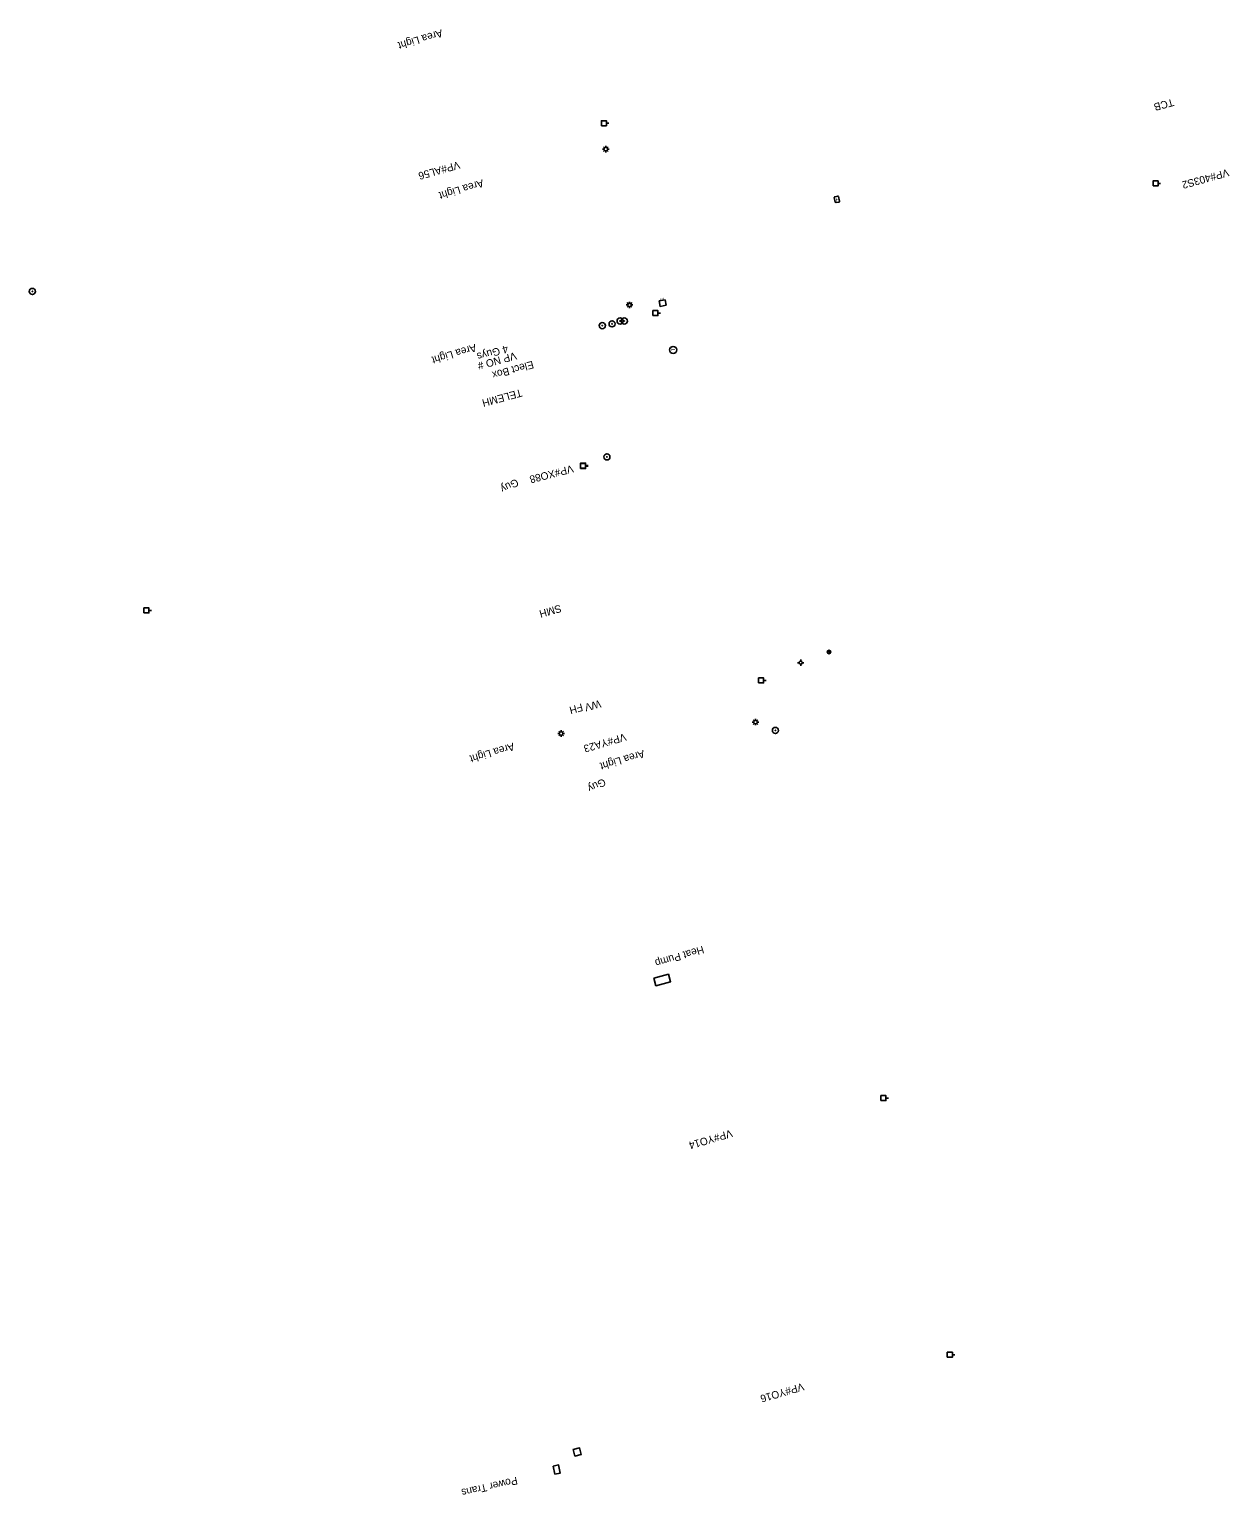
# Model space of a CAD drawing. Extents: x 3872070 to 3879223, y 293944 to 310567.
# Drawn here: x 3875879 to 3876357, y 294304 to 294887 of the extents above; entities that cross this region are included whole.
import ezdxf

# ---------------------------------------------------------------- set-up
doc = ezdxf.new("R2010")
doc.units = 0
for name, color, linetype in [('Level 33', 7, 'Continuous'), ('Level 34', 7, 'Continuous'), ('Level 35', 7, 'Continuous'), ('Level 37', 7, 'Continuous'), ('Level 39', 7, 'Continuous'), ('Level 4', 7, 'Continuous'), ('Level 5', 7, 'Continuous'), ('Level 7', 7, 'Continuous'), ('Level 9', 7, 'Continuous')]:
    doc.layers.add(name, color=color, linetype=linetype)

msp = doc.modelspace()

# ---------------------------------------------------------------- linework, layer by layer
at = {"layer": 'Level 4'}
for p, q in [((3876108.78, 294849.79), (3876109.78, 294849.79)), ((3876107.78, 294839.51), (3876107.2, 294839.51)), ((3876107.99, 294840.03), (3876107.58, 294840.43)), ((3876107.58, 294838.59), (3876107.99, 294839)), ((3876108.5, 294840.24), (3876108.5, 294840.81)), ((3876108.5, 294838.79), (3876108.5, 294838.21)), ((3876109.01, 294840.03), (3876109.42, 294840.43)), ((3876109.42, 294838.59), (3876109.01, 294839)), ((3876109.23, 294839.51), (3876109.8, 294839.51)), ((3876328.28, 294825.87), (3876329.28, 294825.87)), ((3876117.25, 294777.5), (3876116.68, 294777.5)), ((3876117.46, 294778.01), (3876117.06, 294778.42)), ((3876117.06, 294776.58), (3876117.46, 294776.99)), ((3876117.98, 294778.23), (3876117.98, 294778.8)), ((3876117.98, 294776.78), (3876117.98, 294776.2)), ((3876118.49, 294778.01), (3876118.9, 294778.42)), ((3876118.9, 294776.58), (3876118.49, 294776.99)), ((3876118.7, 294777.5), (3876119.28, 294777.5)), ((3876129.24, 294774.26), (3876130.24, 294774.26)), ((3876100.49, 294713.59), (3876101.49, 294713.59)), ((3876100.51, 294713.37), (3876101.51, 294713.37)), ((3875926.71, 294655.95), (3875927.71, 294655.95)), ((3876171.33, 294628.13), (3876172.33, 294628.13)), ((3876167.36, 294611.53), (3876166.79, 294611.53)), ((3876167.58, 294612.04), (3876167.17, 294612.44)), ((3876167.17, 294610.61), (3876167.58, 294611.01)), ((3876168.09, 294612.25), (3876168.09, 294612.83)), ((3876168.6, 294612.04), (3876169.01, 294612.44)), ((3876169.01, 294610.61), (3876168.6, 294611.01)), ((3876168.81, 294611.53), (3876169.39, 294611.53)), ((3876090, 294606.98), (3876089.43, 294606.98)), ((3876090.21, 294607.5), (3876089.81, 294607.9)), ((3876089.81, 294606.06), (3876090.21, 294606.47)), ((3876090.73, 294607.71), (3876090.73, 294608.28)), ((3876090.73, 294606.26), (3876090.73, 294605.68)), ((3876091.24, 294607.5), (3876091.65, 294607.9)), ((3876091.65, 294606.06), (3876091.24, 294606.47)), ((3876091.45, 294606.98), (3876092.03, 294606.98)), ((3876168.09, 294610.8), (3876168.09, 294610.23)), ((3876220.01, 294461.91), (3876221.01, 294461.91)), ((3876246.42, 294359.79), (3876247.42, 294359.79))]:
    msp.add_line(p, q, dxfattribs=at)
for points in [[(3876106.78, 294848.79), (3876106.78, 294850.79), (3876108.78, 294850.79), (3876108.78, 294848.79)], [(3876326.28, 294824.87), (3876326.28, 294826.87), (3876328.28, 294826.87), (3876328.28, 294824.87)], [(3876127.24, 294773.26), (3876127.24, 294775.26), (3876129.24, 294775.26), (3876129.24, 294773.26)], [(3876132.51, 294777.36), (3876130.15, 294776.95), (3876129.77, 294779.1), (3876132.14, 294779.51)], [(3876098.49, 294712.59), (3876098.49, 294714.59), (3876100.49, 294714.59), (3876100.49, 294712.59)], [(3876098.51, 294712.37), (3876098.51, 294714.37), (3876100.51, 294714.37), (3876100.51, 294712.37)], [(3875924.71, 294654.95), (3875924.71, 294656.95), (3875926.71, 294656.95), (3875926.71, 294654.95)], [(3876169.33, 294627.13), (3876169.33, 294629.13), (3876171.33, 294629.13), (3876171.33, 294627.13)], [(3876218.01, 294460.91), (3876218.01, 294462.91), (3876220.01, 294462.91), (3876220.01, 294460.91)], [(3876244.42, 294358.79), (3876244.42, 294360.79), (3876246.42, 294360.79), (3876246.42, 294358.79)]]:
    msp.add_lwpolyline(points, close=True, dxfattribs=at)
for points in [[(3876127.65, 294509.56), (3876133.46, 294511.18), (3876134.29, 294508.21), (3876128.48, 294506.59), (3876127.65, 294509.56)], [(3876095.55, 294322.01), (3876098.08, 294322.69), (3876098.78, 294320.1), (3876096.25, 294319.42), (3876095.55, 294322.01)], [(3876087.59, 294315.47), (3876089.74, 294315.93), (3876090.43, 294312.72), (3876088.28, 294312.26), (3876087.59, 294315.47)]]:
    msp.add_lwpolyline(points, dxfattribs=at)
for centre, radius in [((3876108.5, 294839.51), 0.725), ((3875880.35, 294782.87), 1.22), ((3875880.35, 294782.87), 0.0992), ((3875880.35, 294782.87), 0.0483), ((3876117.98, 294777.5), 0.725), ((3876107.13, 294769.28), 1.22), ((3876107.13, 294769.28), 0.0992), ((3876107.13, 294769.28), 0.0483), ((3876111.03, 294769.99), 1.22), ((3876111.03, 294769.99), 0.0992), ((3876111.03, 294769.99), 0.0483), ((3876114.23, 294771.12), 1.22), ((3876114.23, 294771.12), 0.0992), ((3876114.23, 294771.12), 0.0483), ((3876115.89, 294771.1), 1.22), ((3876115.89, 294771.1), 0.0992), ((3876115.89, 294771.1), 0.0483), ((3876108.96, 294717.06), 1.22), ((3876108.96, 294717.06), 0.0992), ((3876108.96, 294717.06), 0.0483), ((3876168.09, 294611.53), 0.725), ((3876090.73, 294606.98), 0.725), ((3876176.03, 294608.18), 1.22), ((3876176.03, 294608.18), 0.0992), ((3876176.03, 294608.18), 0.0483)]:
    msp.add_circle(centre, radius, dxfattribs=at)
at = {"layer": 'Level 5'}
for p, q in [((3876184.82, 294635.15), (3876185.44, 294635.15)), ((3876186.07, 294636.4), (3876186.07, 294635.76)), ((3876186.07, 294634.52), (3876186.07, 294633.9)), ((3876186.68, 294635.15), (3876187.32, 294635.15)), ((3876196.47, 294639.41), (3876196.83, 294639.41)), ((3876196.83, 294639.41), (3876197.83, 294639.41)), ((3876197.83, 294639.41), (3876198.2, 294639.41))]:
    msp.add_line(p, q, dxfattribs=at)
for centre, radius in [((3876197.33, 294639.41), 0.7), ((3876186.07, 294635.15), 0.625)]:
    msp.add_circle(centre, radius, dxfattribs=at)
msp.add_arc((3876197.33, 294639.41), 0.5, 0, 180, dxfattribs=at)
at = {"layer": 'Level 7'}
msp.add_circle((3876135.33, 294759.6), 1.41, dxfattribs=at)
at = {"layer": 'Level 9'}
msp.add_lwpolyline([(3876199.83, 294818.4), (3876199.45, 294820.27), (3876199.64, 294820.57), (3876200.84, 294820.81), (3876201.14, 294820.62), (3876201.53, 294818.75), (3876201.33, 294818.46), (3876200.13, 294818.21)], close=True, dxfattribs=at)

# ---------------------------------------------------------------- texts
at = {"layer": 'Level 33'}
msp.add_text('SMH', height=3, rotation=195.66735, dxfattribs=at).set_placement((3876090.37, 294658.3))
at = {"layer": 'Level 34'}
for s, rotation, p in [('Area Light', 196.54835, (3876043.09, 294887.19)), ('VP#AL56', 195.66735, (3876049.99, 294834.72)), ('Area Light', 196.54835, (3876059.4, 294827.49)), ('VP#403S2', 195.66735, (3876355.98, 294831.71)), ('Area Light', 196.54835, (3876056.52, 294762.04)), ('4 Guys', 195.23003, (3876069.21, 294761.57)), ('VP NO #', 195.66735, (3876072.5, 294758.83)), ('Elect Box', 195.23003, (3876079.37, 294755.31)), ('VP#XO88', 194.54258, (3876095.2, 294713.87)), ('Guy', 205.5425, (3876072.92, 294708.48)), ('VP#YA23', 196.45376, (3876116.12, 294607.13)), ('Area Light', 196.54835, (3876071.64, 294603.34)), ('Area Light', 196.54835, (3876123.46, 294600.46)), ('Guy', 204.69938, (3876107.65, 294589.22)), ('Heat Pump', 196.45376, (3876147.07, 294522.53)), ('VP#YO14', 196.45376, (3876158.41, 294449.42)), ('VP#YO16', 196.45376, (3876186.86, 294348.62)), ('Power Trans', 192.7093, (3876073.04, 294311.23))]:
    msp.add_text(s, height=3, rotation=rotation, dxfattribs=at).set_placement(p)
at = {"layer": 'Level 35'}
for s, p in [('FH', (3876098.92, 294618.95)), ('WV', (3876106.08, 294620.35))]:
    msp.add_text(s, height=3, rotation=195.23003, dxfattribs=at).set_placement(p)
at = {"layer": 'Level 37'}
msp.add_text('TELEMH', height=3, rotation=195.23003, dxfattribs=at).set_placement((3876074.75, 294744.07))
at = {"layer": 'Level 39'}
msp.add_text('TCB', height=3, rotation=195.23003, dxfattribs=at).set_placement((3876334.05, 294859.67))
at = {"layer": 'Level 4'}
msp.add_text('E', height=1.41, rotation=99.8, dxfattribs=at).set_placement((3876131.77, 294779.17))
at = {"layer": 'Level 7'}
msp.add_text('T', height=1.41, rotation=90, dxfattribs=at).set_placement((3876136.04, 294759.14))
at = {"layer": 'Level 9'}
msp.add_text('H', height=1.41, rotation=11.67732, dxfattribs=at).set_placement((3876200.17, 294818.73))

doc.saveas('drawing.dxf')
